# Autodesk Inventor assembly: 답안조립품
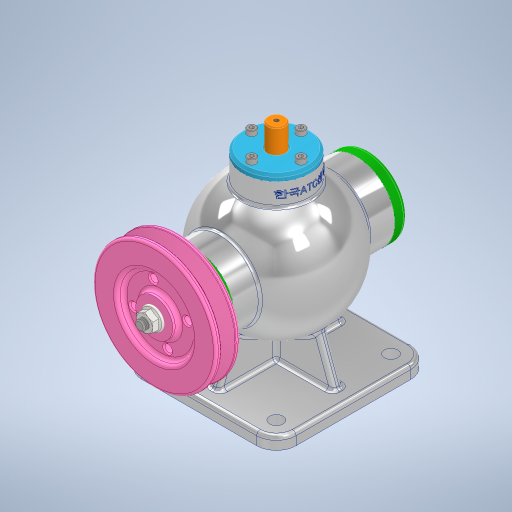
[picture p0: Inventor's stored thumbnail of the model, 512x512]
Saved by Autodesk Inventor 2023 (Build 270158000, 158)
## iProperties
Created: 2023-07
Part Number: 답안조립품
Document SubType Name: Assembly
Designer: Owner
Author: Owner
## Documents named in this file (15)
- C:\Users\Owner\Desktop\730711V1009\답안조립품.iam
- C:\Users\Owner\Desktop\730711V1009\본체.ipt
- C:\Users\Owner\Desktop\730711V1009\뒤커버.ipt
- C:\Users\Owner\Desktop\730711V1009\앞커버.ipt
- C:\Users\Owner\Desktop\730711V1009\상부커버.ipt
- C:\Users\Owner\Desktop\730711V1009\베어링- 6202.ipt
- KS B 2023 - 6202 - 15 x 35 x 11 - 7.8.ipt
- C:\Users\Owner\Desktop\730711V1009\칼라.ipt
- C:\Users\Owner\Desktop\730711V1009\편심축.ipt
- C:\Users\Owner\Desktop\730711V1009\슬라이드.ipt
- C:\Users\Owner\Desktop\730711V1009\키 4 x 4 x 12.ipt
- C:\Users\Owner\Desktop\730711V1009\오일실 15 30 7.ipt
- C:\Users\Owner\Desktop\730711V1009\V-벨트풀리.ipt
- C:\Users\Owner\Desktop\730711V1009\너트 M8.ipt
- C:\Users\Owner\Desktop\730711V1009\볼트 M4 x 16.ipt
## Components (15 placed, 3 different names)
1. KS B 2023 - 6202 - 15 x 35 x 11 - 7.8:1
2. KS B 2023 - 6202 - 15 x 35 x 11 - 7.8:2
3. V-벨트풀리:1
4. ISO 4762 M4 x 16:1
5. ISO 4762 M4 x 16:3
6. ISO 4762 M4 x 16:4
7. ISO 4762 M4 x 16:5
8. ISO 4762 M4 x 16:2
9. ISO 4762 M4 x 16:6
10. ISO 4762 M4 x 16:7
11. ISO 4762 M4 x 16:8
12. ISO 4762 M4 x 16:9
13. ISO 4762 M4 x 16:10
14. ISO 4762 M4 x 16:11
15. ISO 4762 M4 x 16:12
